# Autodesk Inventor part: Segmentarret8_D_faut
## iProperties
Created: 2011-10
Part Number: Segmentarret8_D_faut
Document SubType Name: Modeling
Designer: Bruno
Author: Bruno
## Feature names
1. Base1
